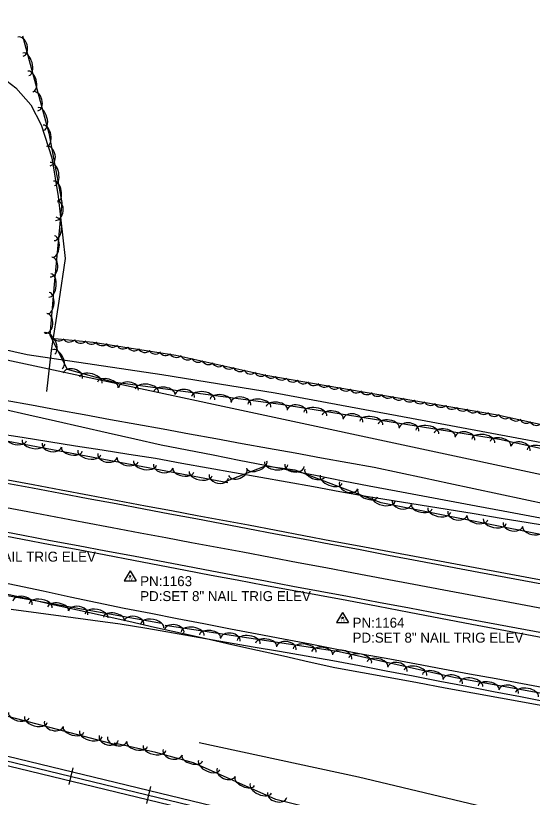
# Model space of a CAD drawing. Extents: x 1441650 to 1491889, y 345904 to 358319.
# Drawn here: x 1456523.8 to 1456782.8, y 351837.8 to 352229.9 of the extents above; entities that cross this region are included whole.
import ezdxf

# ---------------------------------------------------------------- set-up
doc = ezdxf.new("R2010")
doc.units = 0
for name, color, linetype in [('S_DITCHLINE', 7, 'Continuous'), ('S_EDGE_PAVEMENT', 7, 'Continuous'), ('S_PAVEMENT_CROWN', 7, 'Continuous'), ('S_RAILROAD', 7, 'Continuous'), ('S_SECONDARY_CTL', 7, 'Continuous'), ('S_SECONDARY_CTL_ANNOT', 7, 'Continuous'), ('S_SHOULDER', 7, 'Continuous'), ('S_STREAM', 7, 'Continuous'), ('S_TRAILS', 7, 'Continuous'), ('S_TREE', 7, 'Continuous'), ('S_WATER_UTILITIES', 7, 'Continuous')]:
    doc.layers.add(name, color=color, linetype=linetype)

msp = doc.modelspace()

# ---------------------------------------------------------------- linework, layer by layer
at = {"layer": 'S_DITCHLINE'}
for points in [[(1456517.19, 352032.74), (1456530.45, 352029.74), (1456543.7, 352026.73), (1456556.95, 352023.73), (1456570.2, 352020.72), (1456583.46, 352017.72), (1456596.71, 352014.71), (1456609.75, 352012.13), (1456622.8, 352009.55), (1456635.85, 352006.97), (1456648.89, 352004.39), (1456661.94, 352001.82), (1456674.99, 351999.24), (1456688.04, 351996.66), (1456701.08, 351994.08), (1456714.5, 351991.57), (1456727.92, 351989.05), (1456741.33, 351986.54), (1456754.75, 351984.03), (1456768.17, 351981.52), (1456781.58, 351979.01), (1456795, 351976.49)], [(1456513.71, 352020.54), (1456527.08, 352018.43), (1456540.44, 352016.32), (1456553.81, 352014.21), (1456567.18, 352012.1), (1456580.55, 352010), (1456593.92, 352007.89), (1456607.12, 352005.52), (1456620.31, 352003.15), (1456633.51, 352000.78), (1456646.71, 351998.41), (1456659.9, 351996.04), (1456673.1, 351993.67), (1456686.3, 351991.3), (1456699.49, 351988.93), (1456713.02, 351986.73), (1456726.55, 351984.53), (1456740.08, 351982.33), (1456753.61, 351980.13), (1456767.14, 351977.93), (1456780.67, 351975.73), (1456794.2, 351973.53)], [(1456510.42, 351947.13), (1456523.97, 351944.24), (1456537.52, 351941.35), (1456551.07, 351938.46), (1456564.62, 351935.57), (1456578.17, 351932.68), (1456591.5, 351930.12), (1456604.82, 351927.55), (1456618.15, 351924.99), (1456631.47, 351922.42), (1456644.8, 351919.86), (1456658.13, 351917.29), (1456671.45, 351914.73), (1456684.78, 351912.17), (1456698.09, 351909.7), (1456711.4, 351907.23), (1456724.71, 351904.76), (1456738.02, 351902.3), (1456751.33, 351899.83), (1456764.65, 351897.36), (1456777.96, 351894.89), (1456791.27, 351892.43)], [(1456521.6, 351932.2), (1456535.26, 351930.38), (1456548.91, 351928.56), (1456562.56, 351926.74), (1456576.22, 351924.92), (1456589.53, 351922.62), (1456602.85, 351920.31), (1456616.16, 351918), (1456629.48, 351915.7), (1456642.79, 351913.39), (1456656.1, 351911.08), (1456669.42, 351908.78), (1456682.73, 351906.47), (1456696.18, 351903.88), (1456709.63, 351901.3), (1456723.08, 351898.71), (1456736.52, 351896.12), (1456749.97, 351893.53), (1456763.42, 351890.95), (1456776.87, 351888.36), (1456790.32, 351885.77)]]:
    msp.add_lwpolyline(points, dxfattribs=at)
at = {"layer": 'S_EDGE_PAVEMENT'}
for points in [[(1456519.39, 351995.46), (1456532.23, 351993.07), (1456546.2, 351990.43), (1456560.17, 351987.79), (1456574.15, 351985.15), (1456588.12, 351982.51), (1456601.13, 351980.05), (1456614.14, 351977.6), (1456627.16, 351975.14), (1456640.17, 351972.68), (1456654.05, 351970.07), (1456667.93, 351967.46), (1456681.81, 351964.85), (1456695.69, 351962.23), (1456710.78, 351959.37), (1456725.86, 351956.51), (1456740.94, 351953.65), (1456756.02, 351950.78), (1456778.58, 351946.61), (1456801.15, 351942.44)], [(1456514.37, 351971.76), (1456527.48, 351969.3), (1456541.33, 351966.7), (1456555.18, 351964.1), (1456569.02, 351961.5), (1456582.87, 351958.9), (1456595.98, 351956.42), (1456609.09, 351953.94), (1456622.2, 351951.46), (1456635.31, 351948.97), (1456649.01, 351946.4), (1456662.71, 351943.82), (1456676.42, 351941.25), (1456690.12, 351938.67), (1456705.69, 351935.76), (1456721.25, 351932.85), (1456736.82, 351929.93), (1456752.39, 351927.02), (1456774.91, 351922.81), (1456797.44, 351918.6)]]:
    msp.add_lwpolyline(points, dxfattribs=at)
at = {"layer": 'S_PAVEMENT_CROWN'}
msp.add_lwpolyline([(1456516.53, 351983.7), (1456529.83, 351981.18), (1456543.93, 351978.51), (1456558.04, 351975.85), (1456572.14, 351973.18), (1456586.24, 351970.52), (1456599.1, 351968.11), (1456611.95, 351965.7), (1456624.8, 351963.29), (1456637.65, 351960.88), (1456651.52, 351958.27), (1456665.38, 351955.67), (1456679.24, 351953.06), (1456693.11, 351950.45), (1456708.25, 351947.62), (1456723.4, 351944.79), (1456738.54, 351941.96), (1456753.69, 351939.13), (1456776.85, 351934.76), (1456800.01, 351930.39)], dxfattribs=at)
at = {"layer": 'S_RAILROAD'}
for p, q in [((1456552.51, 351852.6), (1456550.46, 351844.17)), ((1456552.05, 351850.69), (1456552.04, 351850.65)), ((1456550.94, 351846.11), (1456550.96, 351846.21)), ((1456591.38, 351843.17), (1456589.34, 351834.74)), ((1456590.92, 351841.26), (1456590.91, 351841.23))]:
    msp.add_line(p, q, dxfattribs=at)
for points in [[(1455456.15, 352116.32), (1456682.67, 351819.03)], [(1455455.77, 352113.97), (1456682.11, 351816.72)], [(1455455.4, 352111.66), (1456681.56, 351814.45)], [(1456551.46, 351848.39), (1456551.49, 351848.38)], [(1456590.33, 351838.96), (1456590.36, 351838.96)]]:
    msp.add_lwpolyline(points, dxfattribs=at)
at = {"layer": 'S_SECONDARY_CTL'}
for p, q in [((1456581.21, 351951.36), (1456578.2, 351946.4)), ((1456581.21, 351951.36), (1456584.16, 351946.4)), ((1456578.2, 351946.4), (1456584.16, 351946.4)), ((1456687.72, 351930.52), (1456684.71, 351925.57)), ((1456687.72, 351930.52), (1456690.67, 351925.57)), ((1456684.71, 351925.57), (1456690.67, 351925.57))]:
    msp.add_line(p, q, dxfattribs=at)
for centre, radius in [((1456581.21, 351948.75), 0.311), ((1456581.21, 351948.75), 0.183), ((1456581.21, 351948.75), 0.103), ((1456687.72, 351927.91), 0.311), ((1456687.72, 351927.91), 0.183), ((1456687.72, 351927.91), 0.103)]:
    msp.add_circle(centre, radius, dxfattribs=at)
at = {"layer": 'S_SHOULDER'}
for points in [[(1456519.82, 351997.14), (1456532.52, 351994.76), (1456546.63, 351992.1), (1456560.74, 351989.44), (1456574.85, 351986.77), (1456588.96, 351984.11), (1456601.88, 351981.69), (1456614.79, 351979.27), (1456627.7, 351976.85), (1456640.61, 351974.43), (1456654.48, 351971.8), (1456668.34, 351969.18), (1456682.21, 351966.55), (1456696.08, 351963.93), (1456711.27, 351961.1), (1456726.45, 351958.28), (1456741.64, 351955.45), (1456756.83, 351952.62), (1456779.26, 351948.41), (1456801.68, 351944.19)], [(1456514.05, 351969.78), (1456527.21, 351967.36), (1456541.14, 351964.71), (1456555.06, 351962.05), (1456568.99, 351959.39), (1456582.92, 351956.73), (1456595.89, 351954.26), (1456608.87, 351951.79), (1456621.84, 351949.31), (1456634.82, 351946.84), (1456648.58, 351944.3), (1456662.35, 351941.75), (1456676.11, 351939.21), (1456689.88, 351936.67), (1456705.52, 351933.68), (1456721.16, 351930.68), (1456736.8, 351927.68), (1456752.44, 351924.69), (1456774.68, 351920.5), (1456796.91, 351916.32)]]:
    msp.add_lwpolyline(points, dxfattribs=at)
at = {"layer": 'S_STREAM'}
for points in [[(1456514.99, 352200.39), (1456523.88, 352193.79), (1456531.42, 352185.19), (1456536.58, 352175.2), (1456541.9, 352158.52), (1456545.13, 352139.23), (1456548.58, 352108.12), (1456545.38, 352086.75), (1456541.61, 352062.01), (1456539.26, 352041.34)], [(1456615.77, 351865.35), (1456695.66, 351848.16), (1456791.55, 351825.27), (1456839.87, 351813.99), (1456887.66, 351801.8), (1456991.3, 351776.75), (1457048.85, 351760.81), (1457118.67, 351745.25)]]:
    msp.add_lwpolyline(points, dxfattribs=at)
at = {"layer": 'S_TRAILS'}
msp.add_lwpolyline([(1457268.76, 352049.42), (1457263.88, 352006.18), (1457257.72, 351978.65), (1457254.6, 351968.16), (1457245.15, 351954.83), (1457236.81, 351943.99), (1457223.45, 351940.54), (1457207.24, 351942.59), (1457150.06, 351951.48), (1457102.66, 351954.44), (1457056.72, 351964.71), (1457003.28, 351976.66), (1456951.11, 351985.66), (1456898.64, 351994), (1456833.2, 352007.16), (1456729.36, 352026.45), (1456653.98, 352040.61), (1456597.16, 352049.77), (1456529.59, 352059.81), (1456484.15, 352069.96), (1456466.33, 352073.63), (1456452.89, 352073.26), (1456447.05, 352071.68)], dxfattribs=at)
at = {"layer": 'S_TREE'}
for points in [[(1456630.12, 351995.51), (1456477.18, 352024.4), (1456471.45, 352032.1), (1456473.31, 352050.11), (1456482.73, 352078.74), (1456483.51, 352085.67), (1456476.37, 352086.23), (1456463.23, 352076.24), (1456448.12, 352078.81), (1456442.08, 352105.43), (1456443.83, 352124.84), (1456458.84, 352129.81), (1456467.11, 352140.65), (1456467.35, 352162.41), (1456471.54, 352182.05), (1456469.23, 352195.67), (1456465.52, 352206.8), (1456472.21, 352219.61), (1456487.26, 352229.93)], [(1456527.22, 352219.77), (1456540.48, 352171.06), (1456547.01, 352136.18), (1456543.07, 352095.02), (1456540.96, 352069.62), (1456549.68, 352052.53), (1456572.48, 352046.22), (1456656.69, 352034.98), (1456766.41, 352017.4), (1456860.65, 351996.7), (1456917.81, 351986.67), (1456968.36, 351975.61), (1457003.67, 351974.34), (1457037, 351966.87), (1457091.18, 351954.76), (1457133.43, 351949.73), (1457169.05, 351946.81), (1457212.77, 351938.5), (1457241.33, 351937.88), (1457252.05, 351948.92), (1457259.75, 351971.53), (1457265.42, 351993.28), (1457268.88, 352004.52)], [(1456946.77, 352049.56), (1456954, 352019.61), (1456952.33, 351998.8), (1456935.11, 351992.63), (1456885.1, 352002.92), (1456810.32, 352019.63), (1456765.4, 352029.56), (1456649.16, 352049.43), (1456604.07, 352059.51), (1456562.66, 352066.04), (1456541.64, 352068)], [(1456518.45, 352037.05), (1456531.67, 352034.64), (1456544.89, 352032.23), (1456558.1, 352029.82), (1456571.32, 352027.42), (1456584.54, 352025.01), (1456597.76, 352022.6), (1456610.98, 352020.2), (1456624.2, 352017.79), (1456637.42, 352015.38), (1456650.64, 352012.98), (1456663.86, 352010.57), (1456677.07, 352008.16), (1456690.29, 352005.75), (1456703.51, 352003.35), (1456716.02, 352000.68), (1456728.54, 351998.01), (1456741.05, 351995.34), (1456753.56, 351992.67), (1456766.07, 351990), (1456778.58, 351987.33), (1456791.1, 351984.66)], [(1456518.45, 352037.05), (1456531.67, 352034.64), (1456544.89, 352032.23), (1456558.1, 352029.82), (1456571.32, 352027.42), (1456584.54, 352025.01), (1456597.76, 352022.6), (1456610.98, 352020.2), (1456624.2, 352017.79), (1456637.42, 352015.38), (1456650.64, 352012.98), (1456663.86, 352010.57), (1456677.07, 352008.16), (1456690.29, 352005.75), (1456703.51, 352003.35), (1456716.02, 352000.68), (1456728.54, 351998.01), (1456741.05, 351995.34), (1456753.56, 351992.67), (1456766.07, 351990), (1456778.58, 351987.33), (1456791.1, 351984.66)], [(1457347.72, 351846.82), (1457259.29, 351869.82), (1457150.71, 351895.35), (1457088.32, 351909.3), (1456973.99, 351938.99), (1456924.65, 351950.02), (1456900.56, 351955.26), (1456869.4, 351952.76), (1456813.77, 351964.27), (1456707.01, 351985.55), (1456663.97, 352001.96), (1456648.89, 352003.9), (1456628.29, 351995.91)], [(1456246.96, 351990.53), (1456286.73, 351984.6), (1456314.34, 351975.61), (1456343.86, 351964.98), (1456360.66, 351964.23), (1456378.14, 351966.08), (1456406.38, 351963.93), (1456435.2, 351957.55), (1456463.95, 351949.36), (1456500.87, 351942.44), (1456596.84, 351925.19)], [(1456574.65, 351863.95), (1456486.65, 351886.99), (1456411.35, 351900.56), (1456320.17, 351919.77), (1456184.71, 351951.86)], [(1456516, 351940.56), (1456528.91, 351937.67), (1456541.82, 351934.78), (1456554.73, 351931.88), (1456567.64, 351928.99), (1456580.55, 351926.1), (1456593.46, 351923.21), (1456606.37, 351920.31), (1456619.28, 351917.42), (1456632.19, 351914.53), (1456645.1, 351911.64), (1456658.01, 351908.75), (1456670.92, 351905.85), (1456683.83, 351902.96), (1456697.67, 351900.42), (1456711.5, 351897.89), (1456725.34, 351895.35), (1456739.17, 351892.81), (1456753.01, 351890.27), (1456766.84, 351887.74), (1456780.68, 351885.2), (1456794.51, 351882.66)], [(1456516, 351940.56), (1456528.91, 351937.67), (1456541.82, 351934.78), (1456554.73, 351931.88), (1456567.64, 351928.99), (1456580.55, 351926.1), (1456593.46, 351923.21), (1456606.37, 351920.31), (1456619.28, 351917.42), (1456632.19, 351914.53), (1456645.1, 351911.64), (1456658.01, 351908.75), (1456670.92, 351905.85), (1456683.83, 351902.96), (1456697.67, 351900.42), (1456711.5, 351897.89), (1456725.34, 351895.35), (1456739.17, 351892.81), (1456753.01, 351890.27), (1456766.84, 351887.74), (1456780.68, 351885.2), (1456794.51, 351882.66)], [(1456598.75, 351924.13), (1456686.06, 351910.97), (1456743.52, 351898.13), (1456793.9, 351888.95), (1456816.98, 351884.21), (1456842.02, 351874.01), (1456861.09, 351870.49), (1456889.07, 351872.98), (1456934.56, 351864.11), (1456964.71, 351857.37), (1457007.79, 351847.74), (1457051.75, 351837.91), (1457091.09, 351829.12), (1457165.52, 351812.48), (1457202.07, 351804.31), (1457267.07, 351790.49), (1457300, 351783.98), (1457347.16, 351770.87), (1457399.34, 351758.41), (1457426.78, 351748.95), (1457472.56, 351738.71), (1457528.33, 351726.24), (1457565.01, 351719.11), (1457614.77, 351707.89)], [(1456935.41, 351768.32), (1456757.49, 351810.91), (1456654.24, 351836.69), (1456612.99, 351855.17), (1456594.02, 351860.27), (1456573.25, 351864.94)]]:
    msp.add_lwpolyline(points, dxfattribs=at)
for centre, start, end in [((1456545.4, 352070.39), 213.8777, 315.4746), ((1456550.71, 352069.83), 213.8777, 315.4746), ((1456556.32, 352069.27), 213.8777, 315.4746), ((1456561.74, 352068.76), 213.8777, 315.4746), ((1456567.16, 352068.02), 210.2382, 311.8351), ((1456572.39, 352067.27), 210.2382, 311.8351), ((1456577.65, 352066.37), 210.2382, 311.8351), ((1456583.22, 352065.46), 210.2382, 311.8351), ((1456588.6, 352064.61), 210.2382, 311.8351), ((1456593.84, 352063.82), 210.2382, 311.8351), ((1456599.07, 352063.06), 210.2382, 311.8351), ((1456604.33, 352062.16), 210.2382, 311.8351), ((1456610, 352060.88), 206.6009, 308.1978), ((1456615.31, 352059.69), 206.6009, 308.1978), ((1456620.49, 352058.56), 206.6009, 308.1978), ((1456625.66, 352057.48), 206.6009, 308.1978), ((1456630.85, 352056.25), 206.6009, 308.1978), ((1456636.36, 352054.98), 206.6009, 308.1978), ((1456641.67, 352053.79), 206.6009, 308.1978), ((1456646.85, 352052.67), 206.6009, 308.1978), ((1456651.91, 352051.73), 209.5037, 311.1006), ((1456657.15, 352050.76), 209.5037, 311.1006), ((1456662.71, 352049.78), 209.5037, 311.1006), ((1456668.08, 352048.86), 209.5037, 311.1006), ((1456673.31, 352048), 209.5037, 311.1006), ((1456678.53, 352047.18), 209.5037, 311.1006), ((1456683.78, 352046.21), 209.5037, 311.1006), ((1456689.34, 352045.23), 209.5037, 311.1006), ((1456694.7, 352044.31), 209.5037, 311.1006), ((1456699.93, 352043.45), 209.5037, 311.1006), ((1456705.15, 352042.63), 209.5037, 311.1006), ((1456710.4, 352041.66), 209.5037, 311.1006), ((1456715.96, 352040.68), 209.5037, 311.1006), ((1456721.32, 352039.76), 209.5037, 311.1006), ((1456726.56, 352038.9), 209.5037, 311.1006), ((1456731.78, 352038.08), 209.5037, 311.1006), ((1456737.02, 352037.11), 209.5037, 311.1006), ((1456742.58, 352036.13), 209.5037, 311.1006), ((1456747.95, 352035.21), 209.5037, 311.1006), ((1456753.18, 352034.35), 209.5037, 311.1006), ((1456758.4, 352033.53), 209.5037, 311.1006), ((1456763.64, 352032.56), 209.5037, 311.1006), ((1456769.3, 352031.39), 206.7365, 308.3334), ((1456774.61, 352030.22), 206.7365, 308.3334), ((1456779.8, 352029.11), 206.7365, 308.3334), ((1456784.97, 352028.04), 206.7365, 308.3334)]:
    msp.add_arc(centre, 3.64, start, end, dxfattribs=at)
for centre, major_axis, ratio, start_param, end_param in [((1456526.22, 352214.37), (-1.3, 4.78), 0.68531, 3.141593, 6.283185), ((1456528.9, 352205.5), (-1.54, 5.66), 0.550079, 3.141593, 6.283185), ((1456531.23, 352196.95), (-1.4, 5.16), 0.540699, 3.141593, 6.283185), ((1456533.69, 352186.94), (-1.3, 4.78), 0.68531, 3.141593, 6.283185), ((1456536.37, 352178.07), (-1.54, 5.66), 0.550079, 3.141593, 6.283185), ((1456538.59, 352169.67), (-0.98, 5.26), 0.540699, 3.141593, 6.283185), ((1456540.23, 352159.49), (-0.91, 4.87), 0.68531, 3.141593, 6.283185), ((1456542.19, 352150.44), (-1.08, 5.77), 0.550079, 3.141593, 6.283185), ((1456543.82, 352141.72), (-0.98, 5.26), 0.540699, 3.141593, 6.283185), ((1456544.24, 352132.16), (0.47, 4.93), 0.68531, 3.141593, 6.283185), ((1456543.61, 352122.92), (0.56, 5.84), 0.550079, 3.141593, 6.283185), ((1456542.77, 352114.09), (0.51, 5.32), 0.540699, 3.141593, 6.283185), ((1456541.53, 352103.86), (0.47, 4.93), 0.68531, 3.141593, 6.283185), ((1456540.91, 352094.59), (0.49, 5.85), 0.550079, 3.141593, 6.283185), ((1456540.17, 352085.76), (0.44, 5.33), 0.540699, 3.141593, 6.283185), ((1456539.06, 352075.51), (0.41, 4.94), 0.68531, 3.141593, 6.283185), ((1456540.68, 352065.5), (-2.67, 5.23), 0.550079, 3.141593, 6.283185), ((1456544.71, 352057.6), (-2.43, 4.76), 0.540699, 3.141593, 6.283185), ((1456552.44, 352049.29), (-4.78, 1.32), 0.685311, 3.141593, 6.283185), ((1456561.44, 352047.07), (-5.66, 1.56), 0.55008, 3.141593, 6.283185), ((1456569.98, 352044.71), (-5.15, 1.43), 0.540699, 3.141593, 6.283185), ((1456580.39, 352042.76), (-4.91, 0.66), 0.685311, 3.141593, 6.283185), ((1456589.6, 352041.8), (-5.82, 0.78), 0.55008, 3.141593, 6.283185), ((1456598.39, 352040.62), (-5.3, 0.71), 0.540699, 3.141593, 6.283185), ((1456608.57, 352039), (-4.91, 0.66), 0.685311, 3.141593, 6.283185), ((1456617.78, 352038.03), (-5.82, 0.78), 0.55008, 3.141593, 6.283185), ((1456626.57, 352036.86), (-5.3, 0.71), 0.540699, 3.141593, 6.283185), ((1456636.75, 352035.24), (-4.91, 0.66), 0.685311, 3.141593, 6.283185), ((1456645.96, 352034.27), (-5.82, 0.78), 0.55008, 3.141593, 6.283185), ((1456654.75, 352033.1), (-5.3, 0.71), 0.540699, 3.141593, 6.283185), ((1456664.83, 352031.26), (-4.89, 0.78), 0.685311, 3.141593, 6.283185), ((1456674.01, 352030.06), (-5.79, 0.93), 0.55008, 3.141593, 6.283185), ((1456682.77, 352028.65), (-5.28, 0.85), 0.540699, 3.141593, 6.283185), ((1456692.9, 352026.77), (-4.89, 0.78), 0.685311, 3.141593, 6.283185), ((1456702.08, 352025.56), (-5.79, 0.93), 0.55008, 3.141593, 6.283185), ((1456710.84, 352024.16), (-5.28, 0.85), 0.540699, 3.141593, 6.283185), ((1456720.97, 352022.27), (-4.89, 0.78), 0.685311, 3.141593, 6.283185), ((1456730.15, 352021.06), (-5.79, 0.93), 0.55008, 3.141593, 6.283185), ((1456738.91, 352019.66), (-5.28, 0.85), 0.540699, 3.141593, 6.283185), ((1456524.03, 352017.71), (5.25, -0.99), 0.540698, 3.141593, 6.283186), ((1456749.04, 352017.77), (-4.89, 0.78), 0.685311, 3.141593, 6.283185), ((1456758.22, 352016.57), (-5.79, 0.93), 0.55008, 3.141593, 6.283185), ((1456766.85, 352015.13), (-5.22, 1.15), 0.540699, 3.141593, 6.283185), ((1456532.74, 352016.06), (5.77, -1.09), 0.550079, 3.141593, 6.283186), ((1456541.89, 352014.6), (4.87, -0.92), 0.68531, 3.141594, 6.283187), ((1456776.85, 352012.67), (-4.84, 1.06), 0.685311, 3.141593, 6.283185), ((1456785.95, 352010.94), (-5.73, 1.26), 0.55008, 3.141593, 6.283185), ((1456551.96, 352012.43), (5.25, -0.99), 0.540698, 3.141593, 6.283186), ((1456560.67, 352010.79), (5.77, -1.09), 0.550079, 3.141593, 6.283186), ((1456569.82, 352009.33), (4.87, -0.92), 0.68531, 3.141594, 6.283187), ((1456579.9, 352007.16), (5.25, -0.99), 0.540698, 3.141593, 6.283186), ((1456588.61, 352005.51), (5.77, -1.09), 0.550079, 3.141593, 6.283186), ((1456644.78, 352004.56), (4.98, 1.93), 0.537372, 3.140368, 6.28196), ((1456597.75, 352004.05), (4.87, -0.92), 0.68531, 3.141594, 6.283187), ((1456607.83, 352001.88), (5.25, -0.99), 0.540698, 3.141593, 6.283186), ((1456635.09, 352001.08), (4.62, 1.8), 0.681092, 3.139533, 6.281125), ((1456654.4, 352005.31), (5.82, -0.74), 0.545901, 3.138111, 6.279703), ((1456663.61, 352004.39), (4.91, -0.61), 0.680099, 3.135927, 6.27752), ((1456673.71, 352000.5), (5, -1.9), 0.536492, 3.141561, 6.283153), ((1456616.54, 352000.24), (5.77, -1.09), 0.550079, 3.141593, 6.283186), ((1456625.69, 351998.77), (4.87, -0.92), 0.68531, 3.141594, 6.283187), ((1456682, 351997.34), (5.48, -2.09), 0.545799, 3.14156, 6.283152), ((1456690.74, 351994.28), (4.63, -1.77), 0.679978, 3.141539, 6.283132), ((1456700.27, 351990.37), (5, -1.9), 0.536492, 3.141561, 6.283153), ((1456708.26, 351987.45), (5.76, -1.15), 0.545595, 3.141564, 6.283157), ((1456717.39, 351985.89), (4.86, -0.97), 0.679723, 3.141546, 6.283139), ((1456727.44, 351983.62), (5.24, -1.05), 0.536291, 3.141565, 6.283158), ((1456736.14, 351981.89), (5.76, -1.15), 0.545595, 3.141564, 6.283157), ((1456745.27, 351980.33), (4.86, -0.97), 0.679723, 3.141546, 6.283139), ((1456755.32, 351978.06), (5.24, -1.05), 0.536291, 3.141565, 6.283158), ((1456764.02, 351976.33), (5.76, -1.15), 0.545595, 3.141564, 6.283157), ((1456773.15, 351974.77), (4.86, -0.97), 0.679723, 3.141546, 6.283139), ((1456783.2, 351972.51), (5.24, -1.05), 0.536291, 3.141565, 6.283158), ((1456527.19, 351935.29), (-4.88, 0.88), 0.685281, 3.141621, 6.283214), ((1456536.35, 351933.91), (-5.78, 1.04), 0.550056, 3.14161, 6.283203), ((1456545.08, 351932.34), (-5.26, 0.95), 0.540676, 3.14161, 6.283202), ((1456555.17, 351930.26), (-4.88, 0.88), 0.685281, 3.141621, 6.283214), ((1456564.33, 351928.88), (-5.78, 1.04), 0.550056, 3.14161, 6.283203), ((1456573.06, 351927.31), (-5.26, 0.95), 0.540676, 3.14161, 6.283202), ((1456583.15, 351925.23), (-4.88, 0.88), 0.685281, 3.141621, 6.283214), ((1456592.31, 351923.85), (-5.78, 1.04), 0.550056, 3.14161, 6.283203), ((1456603.29, 351921.05), (-4.9, 0.74), 0.681416, 3.141593, 6.283185), ((1456612.49, 351919.93), (-5.8, 0.87), 0.546953, 3.141593, 6.283185), ((1456621.26, 351918.61), (-5.29, 0.8), 0.537626, 3.141593, 6.283185), ((1456631.4, 351916.81), (-4.9, 0.74), 0.681416, 3.141593, 6.283185), ((1456640.6, 351915.69), (-5.8, 0.87), 0.546953, 3.141593, 6.283185), ((1456649.37, 351914.37), (-5.29, 0.8), 0.537626, 3.141593, 6.283185), ((1456659.51, 351912.58), (-4.9, 0.74), 0.681416, 3.141593, 6.283185), ((1456668.71, 351911.45), (-5.8, 0.87), 0.546953, 3.141593, 6.283185), ((1456677.48, 351910.13), (-5.29, 0.8), 0.537626, 3.141593, 6.283185), ((1456687.44, 351908.24), (-4.84, 1.08), 0.681421, 3.141593, 6.283185), ((1456696.53, 351906.47), (-5.73, 1.28), 0.546958, 3.141593, 6.283185), ((1456705.18, 351904.54), (-5.22, 1.17), 0.537631, 3.141593, 6.283185), ((1456715.18, 351902.03), (-4.84, 1.08), 0.681421, 3.141593, 6.283185), ((1456724.27, 351900.27), (-5.73, 1.28), 0.546958, 3.141593, 6.283185), ((1456732.93, 351898.33), (-5.22, 1.17), 0.537631, 3.141593, 6.283185), ((1456742.92, 351895.83), (-4.84, 1.08), 0.681421, 3.141593, 6.283185), ((1456752.17, 351894.41), (-5.77, 1.05), 0.546951, 3.141593, 6.283185), ((1456760.89, 351892.82), (-5.26, 0.96), 0.537624, 3.141593, 6.283185), ((1456770.98, 351890.72), (-4.88, 0.89), 0.681413, 3.141593, 6.283185), ((1456780.14, 351889.31), (-5.77, 1.05), 0.546951, 3.141593, 6.283185), ((1456525.36, 351879.04), (5.17, -1.35), 0.540675, 3.141592, 6.283185), ((1456533.94, 351876.8), (5.68, -1.49), 0.550055, 3.141592, 6.283185), ((1456542.96, 351874.71), (4.79, -1.26), 0.68528, 3.141592, 6.283184), ((1456552.86, 351871.84), (5.17, -1.35), 0.540675, 3.141592, 6.283185), ((1456561.44, 351869.6), (5.68, -1.49), 0.550055, 3.141592, 6.283185), ((1456570.46, 351867.5), (4.79, -1.26), 0.68528, 3.141592, 6.283184), ((1456574.73, 351867.05), (4.83, -1.09), 0.684884, 3.141626, 6.283219), ((1456584.72, 351864.53), (5.22, -1.17), 0.540363, 3.141612, 6.283205), ((1456593.37, 351862.58), (5.73, -1.29), 0.549738, 3.141613, 6.283206), ((1456602.48, 351860.46), (4.79, -1.29), 0.684881, 3.141593, 6.283185), ((1456612.36, 351857.53), (5.16, -1.39), 0.54036, 3.141593, 6.283185), ((1456620.83, 351853.97), (5.36, -2.4), 0.549735, 3.141593, 6.283185), ((1456629.39, 351850.43), (4.52, -2.03), 0.684881, 3.141593, 6.283185), ((1456638.68, 351845.98), (4.88, -2.19), 0.54036, 3.141593, 6.283185), ((1456646.78, 351842.35), (5.36, -2.4), 0.549735, 3.141593, 6.283185), ((1456654.94, 351838.96), (4.81, -1.2), 0.684882, 3.141593, 6.283185)]:
    msp.add_ellipse(centre, major_axis=major_axis, ratio=ratio, start_param=start_param, end_param=end_param, dxfattribs=at)
at = {"layer": 'S_WATER_UTILITIES'}
msp.add_line((1456494.84, 352062.52), (1458511.04, 351630.06), dxfattribs=at)

# ---------------------------------------------------------------- texts
at = {"layer": 'S_SECONDARY_CTL'}
for p in [(1456580.01, 351946.73), (1456686.51, 351925.9)]:
    msp.add_text('TV', height=1.5, rotation=360, dxfattribs=at).set_placement(p)
at = {"layer": 'S_SECONDARY_CTL_ANNOT'}
for s, p in [('PD:SET 8" NAIL TRIG ELEV', (1456478.41, 351956.04)), ('PN:1163', (1456586.21, 351943.75)), ('PD:SET 8" NAIL TRIG ELEV', (1456586.21, 351936.25)), ('PN:1164', (1456692.72, 351922.91)), ('PD:SET 8" NAIL TRIG ELEV', (1456692.72, 351915.41))]:
    msp.add_text(s, height=5, dxfattribs=at).set_placement(p)

doc.saveas('drawing.dxf')
